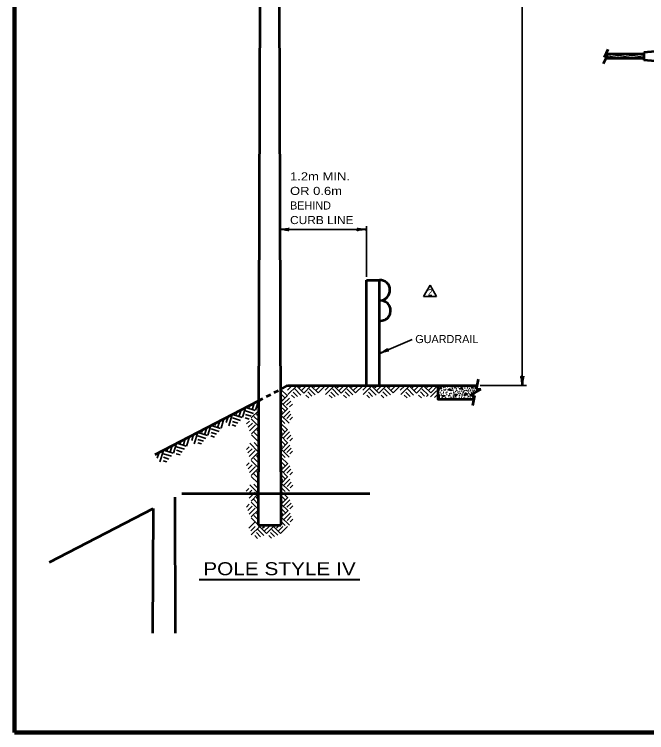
# Model space of a CAD drawing. Extents: x -34 to 821, y -14 to 530.
# Drawn here: x 23.2 to 257.5, y -2.2 to 264 of the extents above; entities that cross this region are included whole.
import ezdxf

# ---------------------------------------------------------------- set-up
doc = ezdxf.new("R2010")
doc.units = 0
doc.header["$LTSCALE"] = 1.2
doc.linetypes.add('SHORT_DASHED', pattern=[2.7, 1.5, -1.2])
doc.layers.add('1', color=7, linetype='Continuous', lineweight=53)

msp = doc.modelspace()

# ---------------------------------------------------------------- linework, layer by layer
at = {"layer": '1', "lineweight": 35}
for p, q in [((211.368, 126.405), (211.368, 441.305)), ((153.61, 184.3), (121.563, 184.3)), ((153.61, 166.743), (153.61, 185.5)), ((177.2, 163.632), (174.8, 159.476)), ((177.2, 163.632), (179.6, 159.476)), ((179.6, 159.476), (174.8, 159.476)), ((158.52, 138.344), (170.528, 143.492)), ((126.047, 126.355), (124.421, 124.729)), ((127.796, 126.355), (124.569, 123.128)), ((127.082, 125.173), (129.373, 122.906)), ((127.673, 126.355), (130.383, 123.645)), ((129.545, 126.355), (128.856, 125.641)), ((131.319, 126.355), (129.619, 124.655)), ((133.069, 126.355), (130.383, 123.645)), ((132.428, 125.247), (134.695, 122.98)), ((133.069, 126.355), (135.705, 123.719)), ((134.818, 126.355), (134.177, 125.715)), ((136.592, 126.355), (134.966, 124.729)), ((138.341, 126.355), (135.705, 123.719)), ((139.967, 126.355), (138.341, 124.729)), ((141.716, 126.355), (138.489, 123.128)), ((141.002, 125.173), (143.293, 122.906)), ((141.593, 126.355), (144.303, 123.645)), ((143.465, 126.355), (142.776, 125.641)), ((145.239, 126.355), (143.539, 124.655)), ((146.989, 126.355), (144.303, 123.645)), ((146.348, 125.247), (148.615, 122.98)), ((146.989, 126.355), (149.625, 123.719)), ((148.738, 126.355), (148.097, 125.715)), ((150.512, 126.355), (148.886, 124.729)), ((152.261, 126.355), (149.625, 123.719)), ((153.887, 126.355), (152.261, 124.729)), ((155.636, 126.355), (152.409, 123.128)), ((154.922, 125.173), (157.213, 122.906)), ((155.513, 126.355), (158.223, 123.645)), ((157.385, 126.355), (156.696, 125.641)), ((159.159, 126.355), (157.459, 124.655)), ((160.909, 126.355), (158.223, 123.645)), ((160.268, 125.247), (162.535, 122.98)), ((160.909, 126.355), (163.545, 123.719)), ((162.658, 126.355), (162.017, 125.715)), ((164.432, 126.355), (162.806, 124.729)), ((166.181, 126.355), (163.545, 123.719)), ((167.807, 126.355), (166.181, 124.729)), ((169.556, 126.355), (166.329, 123.128)), ((168.842, 125.173), (171.133, 122.906)), ((169.433, 126.355), (172.143, 123.645)), ((171.305, 126.355), (170.616, 125.641)), ((173.079, 126.355), (171.379, 124.655)), ((174.829, 126.355), (172.143, 123.645)), ((174.188, 125.247), (176.455, 122.98)), ((174.829, 126.355), (177.465, 123.719)), ((176.578, 126.355), (175.937, 125.715)), ((178.352, 126.355), (176.726, 124.729)), ((180.15, 126.405), (177.465, 123.719)), ((195.75, 126.405), (212.94, 126.405)), ((121.807, 125.13), (124.383, 122.571)), ((121.812, 123.508), (123.401, 121.929)), ((121.823, 120.168), (124.383, 122.744)), ((125.899, 122.857), (126.959, 121.822)), ((126.515, 123.99), (128.092, 122.413)), ((131.221, 122.931), (132.28, 121.871)), ((131.861, 124.064), (133.438, 122.487)), ((139.819, 122.857), (140.879, 121.822)), ((140.435, 123.99), (142.012, 122.413)), ((145.141, 122.931), (146.2, 121.871)), ((145.781, 124.064), (147.358, 122.487)), ((153.739, 122.857), (154.799, 121.822)), ((154.355, 123.99), (155.932, 122.413)), ((159.061, 122.931), (160.12, 121.871)), ((159.701, 124.064), (161.278, 122.487)), ((167.659, 122.857), (168.719, 121.822)), ((168.275, 123.99), (169.852, 122.413)), ((172.981, 122.931), (174.04, 121.871)), ((173.621, 124.064), (175.198, 122.487)), ((176.461, 122.983), (175.837, 122.359)), ((179.625, 124.418), (177.4, 122.194)), ((179.893, 122.983), (178.902, 121.991)), ((112.052, 119.921), (111.377, 117.785)), ((113.631, 120.742), (112.536, 117.279)), ((121.818, 121.864), (122.444, 121.242)), ((121.823, 120.343), (124.471, 117.735)), ((122.905, 119.601), (125.106, 121.817)), ((124.059, 119.113), (125.59, 120.654)), ((107.211, 117.404), (106.505, 115.171)), ((108.79, 118.225), (107.686, 114.676)), ((108.932, 118.3), (112.395, 117.205)), ((110.45, 119.089), (110.184, 118.247)), ((121.828, 118.721), (123.489, 117.071)), ((121.839, 115.264), (124.471, 117.913)), ((125.165, 118.552), (126.193, 119.587)), ((102.373, 114.89), (101.698, 112.754)), ((103.936, 115.702), (102.596, 111.463)), ((103.982, 115.726), (107.542, 114.601)), ((105.609, 116.572), (105.334, 115.645)), ((108.825, 115.728), (110.896, 115.074)), ((108.832, 117.03), (111.81, 116.09)), ((113.618, 117.044), (110.97, 114.413)), ((113.606, 113.302), (111.956, 114.963)), ((113.612, 115.197), (112.919, 115.872)), ((121.833, 117.077), (122.532, 116.407)), ((121.838, 115.571), (124.993, 112.437)), ((122.993, 114.744), (125.194, 116.984)), ((124.147, 114.257), (125.678, 115.798)), ((125.253, 113.718), (126.257, 114.753)), ((97.673, 112.447), (97.407, 111.606)), ((99.275, 113.28), (98.6, 111.144)), ((100.853, 114.1), (99.759, 110.637)), ((103.881, 111.833), (105.262, 111.415)), ((103.951, 113.114), (106.022, 112.459)), ((103.959, 114.416), (106.958, 113.486)), ((108.733, 114.436), (110.124, 113.996)), ((110.27, 113.239), (109.234, 112.211)), ((111.371, 112.493), (109.83, 110.962)), ((113.6, 111.431), (110.969, 114.056)), ((121.844, 113.929), (123.433, 112.351)), ((121.849, 112.53), (124.425, 109.971)), ((92.832, 109.931), (92.557, 109.003)), ((94.433, 110.763), (93.728, 108.53)), ((96.013, 111.584), (94.909, 108.035)), ((96.055, 110.389), (99.033, 109.448)), ((96.155, 111.658), (99.618, 110.564)), ((112.521, 111.817), (110.306, 109.616)), ((113.599, 111.08), (111.022, 108.52)), ((113.593, 109.361), (112.971, 109.987)), ((121.854, 110.908), (123.443, 109.329)), ((121.859, 109.264), (122.485, 108.642)), ((121.865, 107.568), (124.424, 110.144)), ((122.947, 107.001), (125.148, 109.217)), ((86.498, 106.638), (85.823, 104.502)), ((88.076, 107.459), (86.982, 103.996)), ((89.596, 108.249), (88.921, 106.113)), ((91.159, 109.061), (89.819, 104.821)), ((91.182, 107.775), (94.181, 106.845)), ((91.205, 109.085), (94.765, 107.96)), ((95.956, 107.794), (97.347, 107.355)), ((96.048, 109.087), (98.119, 108.432)), ((113.58, 105.595), (111.021, 108.172)), ((113.587, 107.464), (112.008, 109.053)), ((121.864, 107.743), (124.513, 105.135)), ((124.1, 106.513), (125.631, 108.054)), ((125.206, 105.952), (126.235, 106.987)), ((81.656, 104.122), (80.951, 101.889)), ((83.236, 104.943), (82.132, 101.394)), ((83.378, 105.017), (86.841, 103.922)), ((84.896, 105.806), (84.63, 104.964)), ((91.104, 105.192), (92.485, 104.773)), ((91.174, 106.472), (93.245, 105.818)), ((113.568, 101.9), (110.435, 105.055)), ((113.574, 103.73), (111.996, 105.319)), ((121.87, 106.121), (123.531, 104.471)), ((121.875, 104.477), (122.573, 103.807)), ((121.881, 102.664), (124.512, 105.313)), ((123.035, 102.144), (125.236, 104.384)), ((76.819, 101.607), (76.144, 99.471)), ((78.382, 102.419), (77.042, 98.18)), ((78.428, 102.443), (81.988, 101.318)), ((80.055, 103.289), (79.78, 102.362)), ((83.271, 102.445), (85.342, 101.791)), ((83.278, 103.748), (86.256, 102.807)), ((110.166, 103.727), (109.155, 102.698)), ((111.268, 103.008), (109.727, 101.477)), ((112.418, 102.33), (110.202, 100.105)), ((113.567, 101.644), (110.919, 99.013)), ((121.88, 102.971), (125.035, 99.838)), ((121.886, 101.329), (123.475, 99.751)), ((124.189, 101.657), (125.719, 103.198)), ((125.294, 101.118), (126.299, 102.154)), ((78.327, 98.55), (79.708, 98.132)), ((78.397, 99.831), (80.468, 99.176)), ((78.405, 101.133), (81.404, 100.203)), ((83.178, 101.153), (84.57, 100.713)), ((113.549, 96.032), (110.917, 98.656)), ((113.555, 97.902), (111.904, 99.563)), ((113.561, 99.797), (112.868, 100.472)), ((121.89, 99.93), (124.467, 97.371)), ((110.219, 97.839), (109.183, 96.811)), ((111.32, 97.093), (109.779, 95.562)), ((112.47, 96.417), (110.255, 94.216)), ((121.896, 98.308), (123.485, 96.729)), ((121.901, 96.664), (122.527, 96.042)), ((121.907, 94.968), (124.466, 97.544)), ((122.989, 94.401), (125.189, 96.617)), ((113.548, 95.68), (110.971, 93.12)), ((113.536, 92.064), (111.957, 93.653)), ((113.542, 93.961), (112.92, 94.587)), ((121.906, 95.143), (124.555, 92.535)), ((121.911, 93.521), (123.573, 91.871)), ((124.142, 93.913), (125.673, 95.454)), ((125.248, 93.352), (126.277, 94.387)), ((113.529, 90.196), (110.97, 92.772)), ((121.917, 91.877), (122.615, 91.207)), ((121.923, 90.064), (124.554, 92.713)), ((123.077, 89.544), (125.277, 91.784)), ((124.23, 89.057), (125.761, 90.598)), ((110.115, 88.327), (109.104, 87.299)), ((113.517, 86.5), (110.384, 89.655)), ((113.523, 88.33), (111.945, 89.919)), ((121.922, 90.371), (125.076, 87.237)), ((121.927, 88.73), (123.517, 87.151)), ((125.336, 88.518), (126.341, 89.553)), ((111.217, 87.608), (109.676, 86.077)), ((112.367, 86.93), (110.151, 84.705)), ((113.516, 86.244), (110.868, 83.613)), ((121.932, 87.33), (124.508, 84.771)), ((121.937, 85.708), (123.527, 84.129)), ((113.498, 80.632), (110.866, 83.257)), ((113.504, 82.502), (111.853, 84.163)), ((113.51, 84.398), (112.816, 85.072)), ((121.943, 84.064), (122.569, 83.443)), ((121.948, 82.368), (124.508, 84.944)), ((121.948, 82.543), (124.596, 79.935)), ((123.03, 81.802), (125.231, 84.017)), ((124.184, 81.313), (125.715, 82.854)), ((110.168, 82.44), (109.132, 81.411)), ((111.269, 81.693), (109.728, 80.162)), ((112.419, 81.017), (110.204, 78.816)), ((113.497, 80.28), (110.92, 77.721)), ((121.953, 80.921), (123.615, 79.271)), ((121.965, 77.464), (124.596, 80.113)), ((125.29, 80.752), (126.318, 81.788)), ((113.478, 74.796), (110.919, 77.372)), ((113.485, 76.664), (111.906, 78.253)), ((113.491, 78.561), (112.869, 79.187)), ((121.959, 79.277), (122.657, 78.607)), ((121.964, 77.771), (125.118, 74.638)), ((123.118, 76.945), (125.319, 79.184)), ((124.272, 76.457), (125.803, 77.998)), ((112.235, 75.742), (110.011, 73.518)), ((121.969, 76.13), (123.558, 74.551)), ((125.378, 75.918), (126.382, 76.954)), ((112.407, 74.205), (110.823, 72.621)), ((114.111, 74.205), (110.967, 71.061)), ((112.863, 71.901), (114.399, 70.365)), ((113.415, 73.053), (115.647, 70.845)), ((113.991, 74.205), (116.631, 71.565)), ((115.815, 74.205), (115.143, 73.509)), ((117.543, 74.205), (115.887, 72.549)), ((119.247, 74.205), (116.631, 71.565)), ((118.071, 71.973), (119.607, 70.437)), ((118.623, 73.125), (120.831, 70.917)), ((119.247, 74.205), (121.815, 71.637)), ((120.951, 74.205), (120.327, 73.581)), ((122.679, 74.205), (121.095, 72.621)), ((124.383, 74.205), (121.815, 71.637)), ((112.263, 70.797), (113.295, 69.789)), ((117.447, 70.869), (118.479, 69.837))]:
    msp.add_line(p, q, dxfattribs=at)
at = {"layer": '1'}
for p, q in [((114.726, 437.021), (113.526, 74.621)), ((120.877, 391.519), (121.926, 74.621)), ((241.819, 248.153), (243.211, 251.153)), ((284.707, 252.401), (256.387, 249.905)), ((241.507, 245.753), (242.899, 248.753)), ((241.819, 248.153), (242.899, 248.753)), ((256.387, 249.305), (242.347, 249.305)), ((256.387, 247.625), (242.371, 247.625)), ((256.387, 249.905), (256.387, 247.001)), ((284.707, 244.529), (256.387, 247.001)), ((153.61, 126.405), (153.61, 165.543)), ((153.61, 165.543), (158.52, 165.543)), ((158.52, 126.405), (158.52, 165.543)), ((195.082, 128.745), (194.252, 125.091)), ((121.759, 125.021), (124.421, 126.405)), ((124.421, 126.405), (194.55, 126.405)), ((196.052, 125.091), (191.92, 122.75)), ((193.72, 122.75), (191.92, 122.75)), ((193.72, 122.75), (192.889, 119.096)), ((194.252, 125.091), (196.052, 125.091)), ((75.348, 100.897), (113.679, 120.821)), ((85.292, 86.44), (154.892, 86.44)), ((82.63, 85.056), (82.797, 34.656)), ((36.218, 60.932), (74.55, 80.856)), ((74.55, 80.856), (74.397, 34.656)), ((113.526, 74.621), (121.926, 74.621))]:
    msp.add_line(p, q, dxfattribs=at)
at = {"layer": '1', "lineweight": 25}
for p, q in [((242.131, 248.801), (246.331, 249.305)), ((242.371, 247.625), (256.387, 249.305)), ((242.659, 248.249), (251.371, 249.305)), ((247.411, 247.625), (256.387, 248.705)), ((252.427, 247.625), (256.387, 248.081))]:
    msp.add_line(p, q, dxfattribs=at)
at = {"layer": '1', "linetype": 'SHORT_DASHED'}
msp.add_line((113.679, 120.821), (121.759, 125.021), dxfattribs=at)
at = {"layer": '1', "lineweight": 40}
msp.add_line((91.668, 54.483), (151.189, 54.483), dxfattribs=at)
at = {"layer": '1', "lineweight": 158}
msp.add_line((814.88, -2.224), (23.28, -2.224), dxfattribs=at)
msp.add_lwpolyline([(814.88, 523.876), (23.18, 523.776), (23.28, -2.224)], dxfattribs=at)
at = {"layer": '1'}
msp.add_lwpolyline([(180.045, 126.405), (180.045, 121.437), (193.421, 121.437)], dxfattribs=at)
at = {"layer": '1', "lineweight": 35}
for points in [[(181.162, 125.838), (180.721, 125.365), (181.415, 125.318), (181.162, 125.807)], [(184.618, 125.239), (183.845, 124.797), (184.996, 124.591), (184.57, 125.254)], [(189.162, 125.681), (188.057, 125.223), (189.288, 125.081), (189.162, 125.633)], [(192.964, 126.028), (192.522, 125.554), (193.216, 125.507), (192.964, 125.996)], [(181.494, 122.792), (182.74, 122.666), (181.936, 122.366), (181.494, 122.808)], [(186.669, 122.303), (186.385, 123.266), (187.316, 123.061), (186.653, 122.35)], [(190.219, 123.739), (191.039, 123.25), (190.014, 122.745), (190.156, 123.755)]]:
    msp.add_lwpolyline(points, dxfattribs=at)
for centre in [(180.642, 125.933), (182.235, 125.681), (182.772, 125.886), (183.734, 125.996), (184.681, 126.075), (185.422, 125.602), (185.612, 125.349), (186.227, 125.602), (186.7, 125.791), (186.969, 125.239), (187.032, 125.239), (187.631, 125.917), (188.688, 126.028), (189.446, 125.98), (190.077, 125.538), (191.023, 126.091), (191.071, 125.554), (191.623, 126.154), (191.875, 125.333), (192.806, 126.201), (193.895, 125.46), (193.99, 125.917), (180.579, 124.765), (180.752, 122.824), (181.005, 123.834), (181.399, 123.218), (181.51, 124.56), (182.204, 123.487), (182.267, 123.96), (182.362, 124.828), (182.772, 124.781), (183.087, 123.708), (183.15, 125.065), (183.419, 123.092), (183.561, 123.96), (184.129, 122.603), (184.46, 123.36), (184.507, 122.777), (184.949, 123.566), (185.422, 124.718), (185.817, 122.571), (185.864, 123.282), (185.88, 124.607), (186.022, 123.929), (186.669, 124.213), (187.111, 124.544), (187.584, 123.96), (187.915, 123.518), (188.073, 124.229), (188.105, 122.792), (188.531, 123.487), (188.846, 124.339), (189.035, 123.092), (189.051, 122.477), (189.319, 124.923), (189.383, 123.013), (189.398, 123.581), (189.477, 123.944), (189.603, 124.323), (189.935, 124.528), (190.566, 124.67), (190.992, 122.84), (191.102, 124.497), (191.481, 124.844), (191.544, 123.708), (191.607, 124.371), (191.812, 123.36), (192.301, 124.86), (192.317, 124.481), (192.507, 123.771), (193.059, 124.718), (193.185, 124.15), (193.595, 124.639), (194.416, 124.844), (195.236, 124.844), (180.752, 122.114), (181.715, 122.066), (182.898, 121.972), (184.208, 121.703), (184.918, 122.129), (185.344, 121.893), (186.038, 122.066), (186.811, 121.893), (188.026, 122.145), (188.941, 121.877), (189.777, 121.845), (190.108, 121.987), (191.039, 121.766), (191.386, 122.366), (191.655, 122.366), (192.207, 121.782), (193.043, 122.319), (193.122, 121.94)]:
    msp.add_circle(centre, 0.0315, dxfattribs=at)
at = {"layer": '1'}
for centre, start in [((158.583, 161.774), 273.05603), ((158.847, 154.243), 262.79463)]:
    msp.add_arc(centre, 3.769, start, 90.95751, dxfattribs=at)
at = {"layer": '1', "lineweight": 40}
for centre, major_axis, ratio, start_param, end_param in [((122.907, 184.046), (-2.108, 0.211), 0.07063, 3.1407148, 5.41811), ((122.907, 184.046), (-2.108, 0.211), 0.07063, 3.1407148, 5.41811), ((122.872, 184.632), (-2.143, -0.187), 0.122415, 0.8963533, 3.1415927), ((122.872, 184.632), (-2.143, -0.187), 0.122415, 0.8963533, 3.1415927), ((152.301, 183.969), (2.143, 0.187), 0.122415, 0.8963533, 3.1415927), ((152.265, 184.554), (2.108, -0.211), 0.07063, 3.1407148, 5.41811), ((159.593, 139.165), (-1.896, -1.017), 0.122415, 0.8963533, 3.1415927), ((159.856, 138.641), (-2.02, -0.637), 0.07063, 3.1407148, 5.41811), ((211.037, 127.714), (0.187, -2.143), 0.122415, 0.8963533, 3.1415927), ((211.037, 127.714), (0.187, -2.143), 0.122415, 0.8963533, 3.1415927), ((211.622, 127.749), (-0.211, -2.108), 0.07063, 3.1407148, 5.41811), ((211.622, 127.749), (-0.211, -2.108), 0.07063, 3.1407148, 5.41811)]:
    msp.add_ellipse(centre, major_axis=major_axis, ratio=ratio, start_param=start_param, end_param=end_param, dxfattribs=at)

# ---------------------------------------------------------------- texts
at = {"layer": '1'}
for s, height, width, p in [('1.2m MIN.', 3, 1.2, (125.323, 202.485)), ('OR 0.6m', 3, 1.2, (125.323, 197.085)), ('CURB LINE', 3, 1.1, (125.323, 186.285)), ('2', 2.4, 0.9, (176.436, 159.812)), ('POLE STYLE IV', 4.8, 1.2, (93.16, 56.141))]:
    msp.add_text(s, height=height, dxfattribs=dict(at, width=width)).set_placement(p)
for s, p in [('BEHIND', (125.323, 191.685)), ('GUARDRAIL', (171.715, 142.172))]:
    msp.add_text(s, height=3, dxfattribs=at).set_placement(p)

doc.saveas('drawing.dxf')
